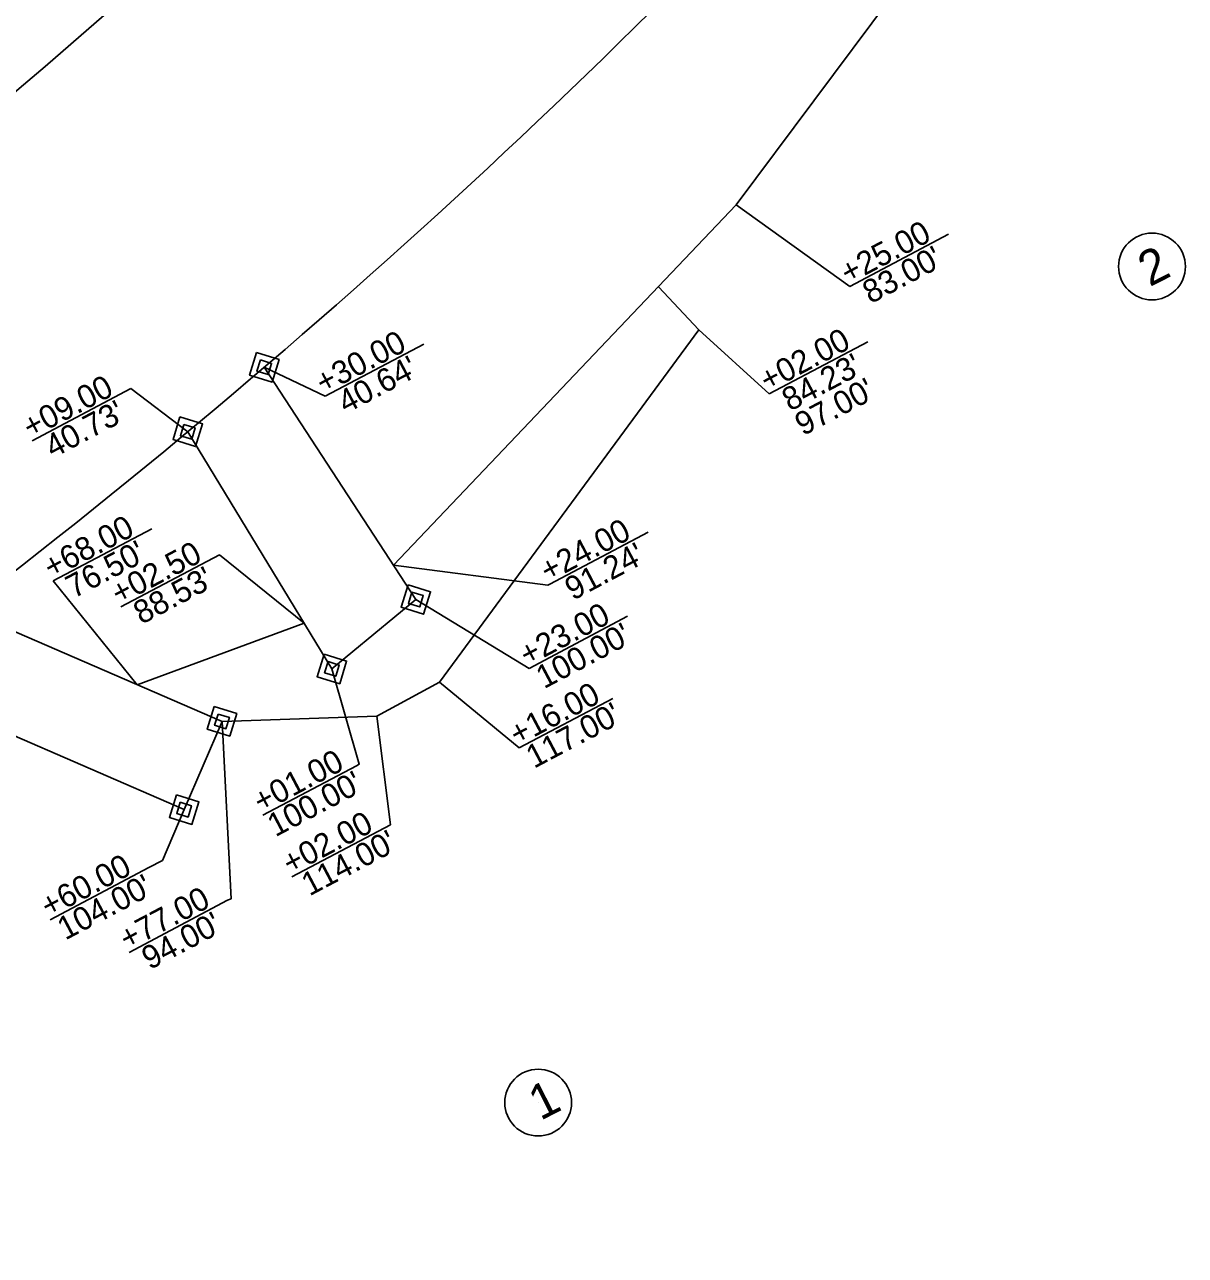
# Model space of a CAD drawing. Extents: x 1487704 to 1489071, y 498271 to 499440.
# Drawn here: x 1488353.7 to 1488604.1, y 498492.4 to 498757.9 of the extents above; entities that cross this region are included whole.
import ezdxf

# ---------------------------------------------------------------- set-up
doc = ezdxf.new("R2010")
doc.units = 0
for name, color, linetype in [('Prop Easement Construction', 7, 'Continuous'), ('Prop Easement Construction Station Offsets', 7, 'Continuous'), ('Prop Easement Permanent Drainage', 7, 'Continuous'), ('Prop Easement Permanent Drainage Station Offsets', 7, 'Continuous'), ('Prop Easement Temporary Drainage', 7, 'Continuous'), ('Prop Easement Temporary Drainage Station Offsets', 7, 'Continuous'), ('Prop ROW Marker CELL', 7, 'Continuous'), ('Prop ROW Permanent Easement CELL', 7, 'Continuous'), ('Prop ROW RW Lines', 7, 'Continuous'), ('Prop ROW Text', 7, 'Continuous')]:
    doc.layers.add(name, color=color, linetype=linetype)

msp = doc.modelspace()

# ---------------------------------------------------------------- linework, layer by layer
at = {"layer": 'Prop Easement Construction'}
for p, q in [((1488507.15, 498718.97), (1488580.63, 498817.39)), ((1488433.23, 498641.25), (1488507.15, 498718.97)), ((1488377.96, 498615.47), (1488413.94, 498628.77))]:
    msp.add_line(p, q, dxfattribs=at)
at = {"layer": 'Prop Easement Construction Station Offsets'}
for p, q in [((1488552.94, 498712.63), (1488531.68, 498701.4)), ((1488381.08, 498649.08), (1488359.81, 498637.85)), ((1488488.2, 498648.36), (1488466.94, 498637.13)), ((1488395.68, 498643.47), (1488374.41, 498632.24))]:
    msp.add_line(p, q, dxfattribs=at)
for points in [[(1488531.68, 498701.4), (1488507.15, 498718.97), (1488507.15, 498718.97)], [(1488395.68, 498643.47), (1488413.94, 498628.77), (1488413.94, 498628.77)], [(1488466.94, 498637.13), (1488466.55, 498636.93), (1488433.23, 498641.25)], [(1488359.81, 498637.85), (1488377.96, 498615.47), (1488377.96, 498615.47)]]:
    msp.add_lwpolyline(points, dxfattribs=at)
at = {"layer": 'Prop Easement Permanent Drainage'}
for p, q in [((1488405.37, 498683.94), (1488438.05, 498633.85)), ((1488388.87, 498670.03), (1488419.96, 498618.88)), ((1488340.67, 498631.59), (1488396.25, 498607.56)), ((1488419.96, 498618.88), (1488438.05, 498633.85)), ((1488321.79, 498617.36), (1488388.08, 498588.53)), ((1488388.08, 498588.53), (1488396.25, 498607.56))]:
    msp.add_line(p, q, dxfattribs=at)
at = {"layer": 'Prop Easement Permanent Drainage Station Offsets'}
for p, q in [((1488439.77, 498688.94), (1488418.5, 498677.71)), ((1488376.59, 498679.34), (1488355.33, 498668.11)), ((1488483.74, 498630.23), (1488462.47, 498619)), ((1488425.25, 498598), (1488405.05, 498587.33)), ((1488380.48, 498576.01), (1488359.21, 498564.78)), ((1488397.45, 498568.97), (1488376.19, 498557.74))]:
    msp.add_line(p, q, dxfattribs=at)
for points in [[(1488418.5, 498677.71), (1488405.37, 498683.94), (1488405.37, 498683.94)], [(1488376.59, 498679.34), (1488388.87, 498670.03), (1488388.87, 498670.03)], [(1488462.47, 498619), (1488438.05, 498633.85)], [(1488425.25, 498598), (1488425.86, 498598.32), (1488419.96, 498618.88)], [(1488397.45, 498568.97), (1488398.2, 498569.3), (1488396.25, 498607.56)], [(1488380.48, 498576.01), (1488383.42, 498577.56), (1488388.08, 498588.53)]]:
    msp.add_lwpolyline(points, dxfattribs=at)
at = {"layer": 'Prop Easement Temporary Drainage'}
for p, q in [((1488499.11, 498692.01), (1488490.38, 498701.33)), ((1488443.19, 498615.99), (1488499.11, 498692.01)), ((1488429.64, 498608.71), (1488443.19, 498615.99)), ((1488396.25, 498607.56), (1488429.64, 498608.71))]:
    msp.add_line(p, q, dxfattribs=at)
at = {"layer": 'Prop Easement Temporary Drainage Station Offsets'}
for p, q in [((1488535.56, 498689.44), (1488514.29, 498678.22)), ((1488480.53, 498612.5), (1488460.32, 498601.83)), ((1488432.61, 498585.25), (1488411.34, 498574.02))]:
    msp.add_line(p, q, dxfattribs=at)
for points in [[(1488514.29, 498678.22), (1488499.11, 498692.01)], [(1488460.32, 498601.83), (1488443.19, 498615.99)], [(1488432.61, 498585.25), (1488429.64, 498608.71)]]:
    msp.add_lwpolyline(points, dxfattribs=at)
at = {"layer": 'Prop ROW Marker CELL'}
for p, q in [((1488405.37, 498683.94), (1488405.37, 498683.94)), ((1488388.87, 498670.03), (1488388.87, 498670.03)), ((1488438.05, 498633.85), (1488438.05, 498633.85)), ((1488419.96, 498618.88), (1488419.96, 498618.88)), ((1488396.25, 498607.56), (1488396.25, 498607.56)), ((1488388.08, 498588.53), (1488388.08, 498588.53))]:
    msp.add_line(p, q, dxfattribs=at)
at = {"layer": 'Prop ROW Permanent Easement CELL'}
for points in [[(1488403.69, 498687.12), (1488408.55, 498685.62), (1488407.05, 498680.76), (1488402.19, 498682.26)], [(1488404.53, 498685.53), (1488406.96, 498684.78), (1488406.21, 498682.35), (1488403.78, 498683.1)], [(1488387.19, 498673.22), (1488392.05, 498671.72), (1488390.55, 498666.85), (1488385.69, 498668.35)], [(1488388.03, 498671.63), (1488390.46, 498670.87), (1488389.71, 498668.44), (1488387.28, 498669.19)], [(1488436.37, 498637.04), (1488441.24, 498635.53), (1488439.74, 498630.67), (1488434.87, 498632.17)], [(1488437.21, 498635.44), (1488439.65, 498634.69), (1488438.89, 498632.26), (1488436.46, 498633.01)], [(1488418.28, 498622.06), (1488423.14, 498620.56), (1488421.64, 498615.69), (1488416.77, 498617.2)], [(1488419.12, 498620.47), (1488421.55, 498619.72), (1488420.8, 498617.29), (1488418.36, 498618.04)], [(1488394.56, 498610.74), (1488399.43, 498609.24), (1488397.93, 498604.38), (1488393.06, 498605.88)], [(1488395.4, 498609.15), (1488397.84, 498608.4), (1488397.09, 498605.97), (1488394.65, 498606.72)], [(1488386.4, 498591.71), (1488391.26, 498590.21), (1488389.76, 498585.34), (1488384.9, 498586.84)], [(1488387.24, 498590.12), (1488389.67, 498589.37), (1488388.92, 498586.93), (1488386.49, 498587.68)]]:
    msp.add_lwpolyline(points, close=True, dxfattribs=at)
at = {"layer": 'Prop ROW RW Lines'}
for centre, radius, start, end in [((1487403.1, 499856.48), 1462.5, 302.71583, 321.11571), ((1487403.1, 499856.44), 1542.5, 297.83218, 321.11298)]:
    msp.add_arc(centre, radius, start, end, dxfattribs=at)
at = {"layer": 'Prop ROW Text'}
for p, q in [((1488596.85, 498705.68), (1488596.85, 498705.68)), ((1488464.44, 498525.33), (1488464.44, 498525.33))]:
    msp.add_line(p, q, dxfattribs=at)
for centre in [(1488596.85, 498705.68), (1488464.44, 498525.33)]:
    msp.add_circle(centre, 7.2, dxfattribs=at)

# ---------------------------------------------------------------- texts
at = {"layer": 'Prop Easement Construction Station Offsets'}
for s, p in [('+25.00', (1488531.32, 498701.77)), ("83.00'", (1488536.14, 498697.53)), ('+68.00', (1488359.45, 498638.23)), ('+24.00', (1488466.57, 498637.51)), ("76.50'", (1488364.27, 498633.99)), ('+02.50', (1488374.05, 498632.61)), ("91.24'", (1488471.93, 498633.55)), ("88.53'", (1488378.87, 498628.37))]:
    msp.add_text(s, height=5, rotation=27.8351, dxfattribs=at).set_placement(p)
at = {"layer": 'Prop Easement Permanent Drainage Station Offsets'}
for s, p in [('+30.00', (1488418.14, 498678.08)), ("40.64'", (1488422.96, 498673.84)), ('+09.00', (1488354.96, 498668.48)), ("40.73'", (1488359.78, 498664.24)), ('+23.00', (1488462.11, 498619.37)), ("100.00'", (1488465.71, 498614.49)), ('+01.00', (1488404.68, 498587.71)), ("100.00'", (1488407.76, 498582.54)), ('+60.00', (1488358.85, 498565.15)), ("104.00'", (1488362.45, 498560.27)), ('+77.00', (1488375.82, 498558.11)), ("94.00'", (1488380.65, 498553.88))]:
    msp.add_text(s, height=5, rotation=27.8351, dxfattribs=at).set_placement(p)
at = {"layer": 'Prop Easement Temporary Drainage Station Offsets'}
for s, p in [('+02.00', (1488513.93, 498678.59)), ("84.23'", (1488518.75, 498674.35)), ("97.00'", (1488521.55, 498669.05)), ('+16.00', (1488459.96, 498602.21)), ("117.00'", (1488463.56, 498597.32)), ('+02.00', (1488410.98, 498574.39)), ("114.00'", (1488415.11, 498569.79))]:
    msp.add_text(s, height=5, rotation=27.8351, dxfattribs=at).set_placement(p)
at = {"layer": 'Prop ROW Text'}
for s, p in [('2', (1488596.36, 498701.22)), ('1', (1488464.92, 498521.37))]:
    msp.add_text(s, height=7.5, rotation=26.9139, dxfattribs=at).set_placement(p)

doc.saveas('drawing.dxf')
